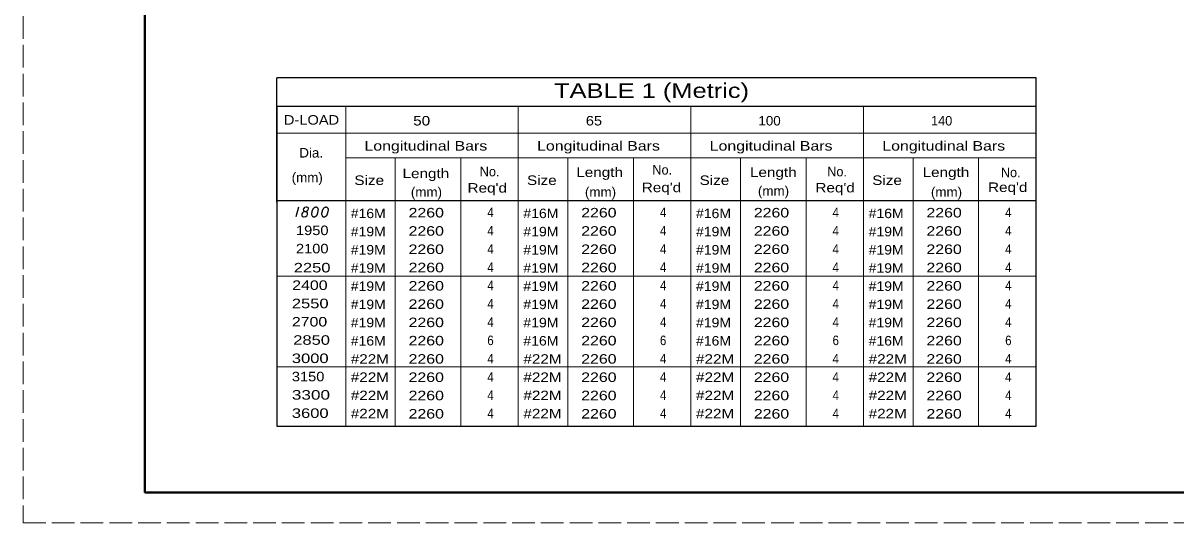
# Model space of a CAD drawing. Extents: x 1170.6 to 1204.6, y 975 to 1019.
# Drawn here: x 1170.59 to 1189.51, y 975.03 to 983.22 of the extents above; entities that cross this region are included whole.
import ezdxf

# ---------------------------------------------------------------- set-up
doc = ezdxf.new("R2010")
doc.units = 0
doc.header["$LTSCALE"] = 0.062
doc.linetypes.add('LONG_DASHED', pattern=[7.5, 6, -1.5])
doc.layers.add('1', color=7, linetype='Continuous', lineweight=13)

msp = doc.modelspace()

# ---------------------------------------------------------------- linework, layer by layer
at = {"layer": '1', "lineweight": 25}
for p, q in [((1187.21383, 982.32592), (1174.75492, 982.32592)), ((1187.21383, 980.285), (1187.21383, 981.85392)), ((1174.75825, 980.31667), (1187.21383, 980.31667)), ((1175.11242, 980.20425), (1175.07025, 980.04692))]:
    msp.add_line(p, q, dxfattribs=at)
at = {"layer": '1'}
for p, q in [((1187.21383, 981.85392), (1187.21383, 980.285)), ((1174.75825, 981.42092), (1187.21383, 981.42092)), ((1175.88583, 981.0125), (1187.21383, 981.0125)), ((1174.75825, 979.07425), (1187.21383, 979.07425)), ((1174.75825, 977.5845), (1187.21383, 977.5845))]:
    msp.add_line(p, q, dxfattribs=at)
at = {"layer": '1', "linetype": 'LONG_DASHED'}
msp.add_lwpolyline([(1170.59275, 975.02625), (1204.59275, 975.02625), (1204.59275, 997.02625), (1170.59275, 997.02625)], close=True, dxfattribs=at)
at = {"layer": '1', "lineweight": 25}
for points in [[(1204.09275, 975.52625), (1172.59275, 975.52625), (1172.59275, 996.52625)], [(1174.75492, 980.285), (1174.75492, 976.61342), (1187.21383, 976.61342), (1187.21383, 982.32592)], [(1187.21383, 981.85392), (1174.75492, 981.85392), (1174.75492, 980.285), (1174.75492, 982.32592)], [(1175.214, 980.13608), (1175.23133, 980.13608), (1175.23625, 980.13733), (1175.25117, 980.14358), (1175.26225, 980.1535), (1175.27467, 980.177), (1175.27342, 980.19433), (1175.26475, 980.2005), (1175.24742, 980.20425), (1175.235, 980.20425), (1175.2115, 980.2005), (1175.20408, 980.19433), (1175.19167, 980.17575), (1175.19042, 980.16958), (1175.19292, 980.151), (1175.19783, 980.14358), (1175.214, 980.13608), (1175.19417, 980.13117), (1175.17558, 980.11258), (1175.16567, 980.094), (1175.16442, 980.08783), (1175.16567, 980.06425), (1175.17683, 980.05192), (1175.19167, 980.04692), (1175.2065, 980.04692), (1175.23008, 980.05308), (1175.24742, 980.06425), (1175.25858, 980.08658), (1175.25983, 980.094), (1175.25858, 980.11383), (1175.24867, 980.13117), (1175.23133, 980.13608)]]:
    msp.add_lwpolyline(points, dxfattribs=at)
at = {"layer": '1', "lineweight": 40}
msp.add_lwpolyline([(1172.59275, 996.52625), (1204.09275, 996.52625), (1204.09275, 975.52625), (1172.59275, 975.52625)], close=True, dxfattribs=at)
at = {"layer": '1'}
for points in [[(1175.88583, 981.85392), (1175.88583, 980.285), (1175.88583, 976.60375)], [(1178.71783, 981.85392), (1178.71783, 980.285), (1178.71783, 976.60375)], [(1181.54983, 981.85392), (1181.54983, 980.285), (1181.54983, 976.60375)], [(1184.38183, 981.85392), (1184.38183, 980.285), (1184.38183, 976.60375)], [(1176.70008, 981.0125), (1176.70008, 980.285), (1176.70008, 976.60375)], [(1177.77383, 981.0125), (1177.77383, 980.285), (1177.77383, 976.60375)], [(1179.53208, 981.0125), (1179.53208, 980.285), (1179.53208, 976.60375)], [(1180.60583, 981.0125), (1180.60583, 980.285), (1180.60583, 976.60375)], [(1182.36408, 981.0125), (1182.36408, 980.285), (1182.36408, 976.60375)], [(1183.43783, 981.0125), (1183.43783, 980.285), (1183.43783, 976.60375)], [(1185.19608, 981.0125), (1185.19608, 980.285), (1185.19608, 976.60375)], [(1186.26983, 981.0125), (1186.26983, 980.285), (1186.26983, 976.60375)]]:
    msp.add_lwpolyline(points, dxfattribs=at)
at = {"layer": '1', "lineweight": 25}
for points in [[(1175.40108, 980.20425), (1175.39858, 980.20425), (1175.39117, 980.203), (1175.38617, 980.20175), (1175.3825, 980.2005), (1175.37625, 980.19808), (1175.36883, 980.19433), (1175.36267, 980.19067), (1175.35642, 980.18567), (1175.35275, 980.18075), (1175.349, 980.1745), (1175.34533, 980.16833), (1175.34158, 980.16092), (1175.33908, 980.15592), (1175.33667, 980.1485), (1175.33292, 980.13608), (1175.32917, 980.1175), (1175.32675, 980.10267), (1175.32675, 980.08908), (1175.32792, 980.07917), (1175.33292, 980.068), (1175.33667, 980.06183), (1175.34283, 980.05433), (1175.35025, 980.04942), (1175.354, 980.04817), (1175.36142, 980.04692), (1175.36758, 980.04692), (1175.3775, 980.04817), (1175.38617, 980.05067), (1175.39242, 980.05433), (1175.40108, 980.06058), (1175.40475, 980.06425), (1175.40975, 980.06925), (1175.41342, 980.07417), (1175.41592, 980.07792), (1175.41842, 980.08408), (1175.41967, 980.08658), (1175.42208, 980.09275), (1175.42458, 980.10017), (1175.42708, 980.10758), (1175.42833, 980.11258), (1175.42958, 980.11633), (1175.43075, 980.12125), (1175.43325, 980.13242), (1175.4345, 980.13858), (1175.43575, 980.14483), (1175.437, 980.1535), (1175.43825, 980.16458), (1175.43825, 980.16833), (1175.437, 980.17325), (1175.43575, 980.17825), (1175.432, 980.18567), (1175.42833, 980.19067), (1175.42458, 980.19433), (1175.41967, 980.19808), (1175.41467, 980.2005), (1175.411, 980.20175), (1175.40725, 980.203)], [(1175.56583, 980.20425), (1175.56333, 980.20425), (1175.55592, 980.203), (1175.55092, 980.20175), (1175.54725, 980.2005), (1175.541, 980.19808), (1175.53358, 980.19433), (1175.52742, 980.19067), (1175.52125, 980.18567), (1175.5175, 980.18075), (1175.51375, 980.1745), (1175.51008, 980.16833), (1175.50633, 980.16092), (1175.50383, 980.15592), (1175.50142, 980.1485), (1175.49767, 980.13608), (1175.494, 980.1175), (1175.4915, 980.10267), (1175.4915, 980.08908), (1175.49275, 980.07917), (1175.49767, 980.068), (1175.50142, 980.06183), (1175.50758, 980.05433), (1175.515, 980.04942), (1175.51875, 980.04817), (1175.52617, 980.04692), (1175.53233, 980.04692), (1175.54225, 980.04817), (1175.55092, 980.05067), (1175.55717, 980.05433), (1175.56583, 980.06058), (1175.5695, 980.06425), (1175.5745, 980.06925), (1175.57817, 980.07417), (1175.58067, 980.07792), (1175.58317, 980.08408), (1175.58442, 980.08658), (1175.58692, 980.09275), (1175.58933, 980.10017), (1175.59183, 980.10758), (1175.59308, 980.11258), (1175.59433, 980.11633), (1175.59558, 980.12125), (1175.598, 980.13242), (1175.59925, 980.13858), (1175.6005, 980.14483), (1175.60175, 980.1535), (1175.603, 980.16458), (1175.603, 980.16833), (1175.60175, 980.17325), (1175.6005, 980.17825), (1175.59675, 980.18567), (1175.59308, 980.19067), (1175.58933, 980.19433), (1175.58442, 980.19808), (1175.57942, 980.2005), (1175.57575, 980.20175), (1175.572, 980.203)]]:
    msp.add_lwpolyline(points, close=True, dxfattribs=at)

# ---------------------------------------------------------------- texts
at = {"layer": '1'}
for s, height, width, p in [('TABLE 1 (Metric)', 0.24, 1.3, (1179.304, 981.99717)), ('D-LOAD', 0.156, 1.15, (1174.87233, 981.55875)), ('50', 0.156, 1.2, (1176.99317, 981.54458)), ('65', 0.156, 1.15, (1179.82517, 981.54458)), ('100', 0.156, 1.05, (1182.65717, 981.54458)), ('Longitudinal Bars', 0.156, 1.25, (1176.19358, 981.13267)), ('Longitudinal Bars', 0.156, 1.25, (1179.02558, 981.13267)), ('Longitudinal Bars', 0.156, 1.25, (1181.85758, 981.13267)), ('Longitudinal Bars', 0.156, 1.25, (1184.68958, 981.13267)), ('Dia.', 0.156, 1.05, (1175.125, 981.01917)), ('(mm)', 0.156, 1.05, (1175, 980.61492)), ('Size', 0.156, 1.2, (1176.02833, 980.56875)), ('Length', 0.156, 1.2, (1176.81867, 980.68075)), ('Size', 0.156, 1.2, (1178.86033, 980.56875)), ('Length', 0.156, 1.2, (1179.66858, 980.69967)), ('Size', 0.156, 1.2, (1181.69233, 980.56875)), ('Length', 0.156, 1.2, (1182.51842, 980.69967)), ('Size', 0.156, 1.2, (1184.52433, 980.56875)), ('Length', 0.156, 1.2, (1185.35042, 980.69967)), ('(mm)', 0.156, 1.05, (1176.95508, 980.37558)), ("Req'd", 0.156, 1.2, (1177.88517, 980.4435)), ('(mm)', 0.156, 1.05, (1179.811, 980.37558)), ("Req'd", 0.156, 1.2, (1180.74375, 980.45058)), ('(mm)', 0.156, 1.05, (1182.64917, 980.3945)), ("Req'd", 0.156, 1.2, (1183.59242, 980.44708)), ('(mm)', 0.156, 1.05, (1185.48725, 980.37558)), ("Req'd", 0.156, 1.2, (1186.42433, 980.45408)), ('#16M', 0.156, 1.1, (1175.9695, 980.02508)), ('2260', 0.156, 1.25, (1176.9175, 980.03675)), ('4', 0.156, 0.9, (1178.20958, 980.04133)), ('#16M', 0.156, 1.1, (1178.8015, 980.02508)), ('2260', 0.156, 1.25, (1179.7495, 980.03675)), ('4', 0.156, 0.9, (1181.04158, 980.04133)), ('#16M', 0.156, 1.1, (1181.6335, 980.02508)), ('2260', 0.156, 1.25, (1182.5815, 980.03675)), ('4', 0.156, 0.9, (1183.87358, 980.04133)), ('#16M', 0.156, 1.1, (1184.4655, 980.02508)), ('2260', 0.156, 1.25, (1185.4135, 980.03675)), ('4', 0.156, 0.9, (1186.70558, 980.04133)), ('1950', 0.156, 1.15, (1175.07025, 979.74708)), ('#19M', 0.156, 1.1, (1175.9695, 979.72658)), ('2260', 0.156, 1.25, (1176.9175, 979.73692)), ('4', 0.156, 0.9, (1178.20958, 979.7415)), ('#19M', 0.156, 1.1, (1178.8015, 979.72658)), ('2260', 0.156, 1.25, (1179.7495, 979.73692)), ('4', 0.156, 0.9, (1181.04158, 979.7415)), ('#19M', 0.156, 1.1, (1181.6335, 979.72658)), ('2260', 0.156, 1.25, (1182.5815, 979.73692)), ('4', 0.156, 0.9, (1183.87358, 979.7415)), ('#19M', 0.156, 1.1, (1184.4655, 979.72658)), ('2260', 0.156, 1.25, (1185.4135, 979.73692)), ('4', 0.156, 0.9, (1186.70558, 979.7415)), ('2100', 0.156, 1.15, (1175.07025, 979.44725)), ('#19M', 0.156, 1.1, (1175.9695, 979.42808)), ('2260', 0.156, 1.25, (1176.9175, 979.43708)), ('4', 0.156, 0.9, (1178.20958, 979.44167)), ('#19M', 0.156, 1.1, (1178.8015, 979.42808)), ('2260', 0.156, 1.25, (1179.7495, 979.43708)), ('4', 0.156, 0.9, (1181.04158, 979.44167)), ('#19M', 0.156, 1.1, (1181.6335, 979.42808)), ('2260', 0.156, 1.25, (1182.5815, 979.43708)), ('4', 0.156, 0.9, (1183.87358, 979.44167)), ('#19M', 0.156, 1.1, (1184.4655, 979.42808)), ('2260', 0.156, 1.25, (1185.4135, 979.43708)), ('4', 0.156, 0.9, (1186.70558, 979.44167)), ('2250', 0.156, 1.3, (1175.03325, 979.13508)), ('#19M', 0.156, 1.1, (1175.9695, 979.12958)), ('2260', 0.156, 1.25, (1176.9175, 979.13725)), ('4', 0.156, 0.9, (1178.20958, 979.14183)), ('#19M', 0.156, 1.1, (1178.8015, 979.12958)), ('2260', 0.156, 1.25, (1179.7495, 979.13725)), ('4', 0.156, 0.9, (1181.04158, 979.14183)), ('#19M', 0.156, 1.1, (1181.6335, 979.12958)), ('2260', 0.156, 1.25, (1182.5815, 979.13725)), ('4', 0.156, 0.9, (1183.87358, 979.14183)), ('#19M', 0.156, 1.1, (1184.4655, 979.12958)), ('2260', 0.156, 1.25, (1185.4135, 979.13725)), ('4', 0.156, 0.9, (1186.70558, 979.14183)), ('2400', 0.156, 1.25, (1175.0085, 978.84758)), ('#19M', 0.156, 1.1, (1175.9695, 978.83108)), ('2260', 0.156, 1.25, (1176.9175, 978.83742)), ('4', 0.156, 0.9, (1178.20958, 978.842)), ('#19M', 0.156, 1.1, (1178.8015, 978.83108)), ('2260', 0.156, 1.25, (1179.7495, 978.83742)), ('4', 0.156, 0.9, (1181.04158, 978.842)), ('#19M', 0.156, 1.1, (1181.6335, 978.83108)), ('2260', 0.156, 1.25, (1182.5815, 978.83742)), ('4', 0.156, 0.9, (1183.87358, 978.842)), ('#19M', 0.156, 1.1, (1184.4655, 978.83108)), ('2260', 0.156, 1.25, (1185.4135, 978.83742)), ('4', 0.156, 0.9, (1186.70558, 978.842)), ('2550', 0.156, 1.3, (1175.00258, 978.54775)), ('#19M', 0.156, 1.1, (1175.9695, 978.53258)), ('2260', 0.156, 1.25, (1176.9175, 978.53758)), ('4', 0.156, 0.9, (1178.20958, 978.54217)), ('#19M', 0.156, 1.1, (1178.8015, 978.53258)), ('2260', 0.156, 1.25, (1179.7495, 978.53758)), ('4', 0.156, 0.9, (1181.04158, 978.54217)), ('#19M', 0.156, 1.1, (1181.6335, 978.53258)), ('2260', 0.156, 1.25, (1182.5815, 978.53758)), ('4', 0.156, 0.9, (1183.87358, 978.54217)), ('#19M', 0.156, 1.1, (1184.4655, 978.53258)), ('2260', 0.156, 1.25, (1185.4135, 978.53758)), ('4', 0.156, 0.9, (1186.70558, 978.54217)), ('2700', 0.156, 1.25, (1175.00258, 978.248)), ('#19M', 0.156, 1.1, (1175.9695, 978.23408)), ('2260', 0.156, 1.25, (1176.9175, 978.23775)), ('4', 0.156, 0.9, (1178.20958, 978.24233)), ('#19M', 0.156, 1.1, (1178.8015, 978.23408)), ('2260', 0.156, 1.25, (1179.7495, 978.23775)), ('4', 0.156, 0.9, (1181.04158, 978.24233)), ('#19M', 0.156, 1.1, (1181.6335, 978.23408)), ('2260', 0.156, 1.25, (1182.5815, 978.23775)), ('4', 0.156, 0.9, (1183.87358, 978.24233)), ('#19M', 0.156, 1.1, (1184.4655, 978.23408)), ('2260', 0.156, 1.25, (1185.4135, 978.23775)), ('4', 0.156, 0.9, (1186.70558, 978.24233)), ('2850', 0.156, 1.3, (1175.02508, 977.94817)), ('#16M', 0.156, 1.1, (1175.9695, 977.93558)), ('2260', 0.156, 1.25, (1176.9175, 977.93792)), ('6', 0.156, 0.9, (1178.20958, 977.9425)), ('#16M', 0.156, 1.1, (1178.8015, 977.93558)), ('2260', 0.156, 1.25, (1179.7495, 977.93792)), ('6', 0.156, 0.9, (1181.04158, 977.9425)), ('#16M', 0.156, 1.1, (1181.6335, 977.93558)), ('2260', 0.156, 1.25, (1182.5815, 977.93792)), ('6', 0.156, 0.9, (1183.87358, 977.9425)), ('#16M', 0.156, 1.1, (1184.4655, 977.93558)), ('2260', 0.156, 1.25, (1185.4135, 977.93792)), ('6', 0.156, 0.9, (1186.70558, 977.9425)), ('3000', 0.156, 1.3, (1175.00258, 977.64833)), ('#22M', 0.156, 1.2, (1175.9695, 977.63708)), ('2260', 0.156, 1.25, (1176.9175, 977.63808)), ('4', 0.156, 0.9, (1178.20958, 977.64267)), ('#22M', 0.156, 1.2, (1178.8015, 977.63708)), ('2260', 0.156, 1.25, (1179.7495, 977.63808)), ('4', 0.156, 0.9, (1181.04158, 977.64267)), ('#22M', 0.156, 1.2, (1181.6335, 977.63708)), ('2260', 0.156, 1.25, (1182.5815, 977.63808)), ('4', 0.156, 0.9, (1183.87358, 977.64267)), ('#22M', 0.156, 1.2, (1184.4655, 977.63708)), ('2260', 0.156, 1.25, (1185.4135, 977.63808)), ('4', 0.156, 0.9, (1186.70558, 977.64267)), ('3150', 0.156, 1.15, (1175.00258, 977.3485)), ('#22M', 0.156, 1.2, (1175.9695, 977.33858)), ('2260', 0.156, 1.25, (1176.9175, 977.33825)), ('4', 0.156, 0.9, (1178.20958, 977.34283)), ('#22M', 0.156, 1.2, (1178.8015, 977.33858)), ('2260', 0.156, 1.25, (1179.7495, 977.33825)), ('4', 0.156, 0.9, (1181.04158, 977.34283)), ('#22M', 0.156, 1.2, (1181.6335, 977.33858)), ('2260', 0.156, 1.25, (1182.5815, 977.33825)), ('4', 0.156, 0.9, (1183.87358, 977.34283)), ('#22M', 0.156, 1.2, (1184.4655, 977.33858)), ('2260', 0.156, 1.25, (1185.4135, 977.33825)), ('4', 0.156, 0.9, (1186.70558, 977.34283)), ('3300', 0.156, 1.35, (1175.00258, 977.04867)), ('#22M', 0.156, 1.2, (1175.9695, 977.04008)), ('2260', 0.156, 1.25, (1176.9175, 977.03842)), ('4', 0.156, 0.9, (1178.20958, 977.043)), ('#22M', 0.156, 1.2, (1178.8015, 977.04008)), ('2260', 0.156, 1.25, (1179.7495, 977.03842)), ('4', 0.156, 0.9, (1181.04158, 977.043)), ('#22M', 0.156, 1.2, (1181.6335, 977.04008)), ('2260', 0.156, 1.25, (1182.5815, 977.03842)), ('4', 0.156, 0.9, (1183.87358, 977.043)), ('#22M', 0.156, 1.2, (1184.4655, 977.04008)), ('2260', 0.156, 1.25, (1185.4135, 977.03842)), ('4', 0.156, 0.9, (1186.70558, 977.043)), ('3600', 0.156, 1.3, (1175.00258, 976.74883)), ('#22M', 0.156, 1.2, (1175.9695, 976.74158)), ('2260', 0.156, 1.25, (1176.9175, 976.73858)), ('4', 0.156, 0.9, (1178.20958, 976.74317)), ('#22M', 0.156, 1.2, (1178.8015, 976.74158)), ('2260', 0.156, 1.25, (1179.7495, 976.73858)), ('4', 0.156, 0.9, (1181.04158, 976.74317)), ('#22M', 0.156, 1.2, (1181.6335, 976.74158)), ('2260', 0.156, 1.25, (1182.5815, 976.73858)), ('4', 0.156, 0.9, (1183.87358, 976.74317)), ('#22M', 0.156, 1.2, (1184.4655, 976.74158)), ('2260', 0.156, 1.25, (1185.4135, 976.73858)), ('4', 0.156, 0.9, (1186.70558, 976.74317))]:
    msp.add_text(s, height=height, dxfattribs=dict(at, width=width)).set_placement(p)
for s, p in [('140', (1185.48917, 981.54458)), ('No.', (1180.91675, 980.73925)), ('No.', (1178.08458, 980.71108)), ('No.', (1183.78558, 980.71108)), ('No.', (1186.63442, 980.697))]:
    msp.add_text(s, height=0.156, dxfattribs=at).set_placement(p)

doc.saveas('drawing.dxf')
